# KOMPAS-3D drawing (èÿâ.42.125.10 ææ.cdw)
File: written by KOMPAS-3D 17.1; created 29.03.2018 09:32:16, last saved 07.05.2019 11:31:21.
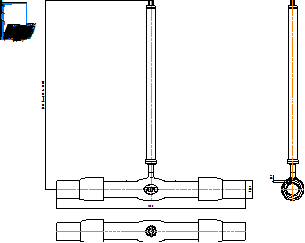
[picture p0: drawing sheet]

Sheet 1: A4, portrait

Title block, sheet 1: name: КШГ.42.125.10 СС; material: Внимание! Данный продукт является объектом авторского права ООО «Торговый Дом АДЛ». / Запрещается изменение, копирование, распространение / (в том числе путем копирования на другие сайты и ресурсы в Интернете) / или любое иное использование информации и объектов без предварительного / согласия правообладателя (ООО «Торговый Дом АДЛ»).; sheets: 1; organisation: ООО "Торговый дом АДЛ"; sheet format: A4; stored path: C:\Users\tra\Desktop\2д чертежи\Шаровые краны БИВАЛ\КШ_Бивал_серия_42_52\KOMPAS 2D\КШГ.42.125.10 СС.cdw

Views: Вид 1, Проекционный вид 2
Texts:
  kka
  adl
  (от 425 до 5000)
Dimensions and other numbers on the sheet: 1500; 140; 12,7; 1:1; 1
